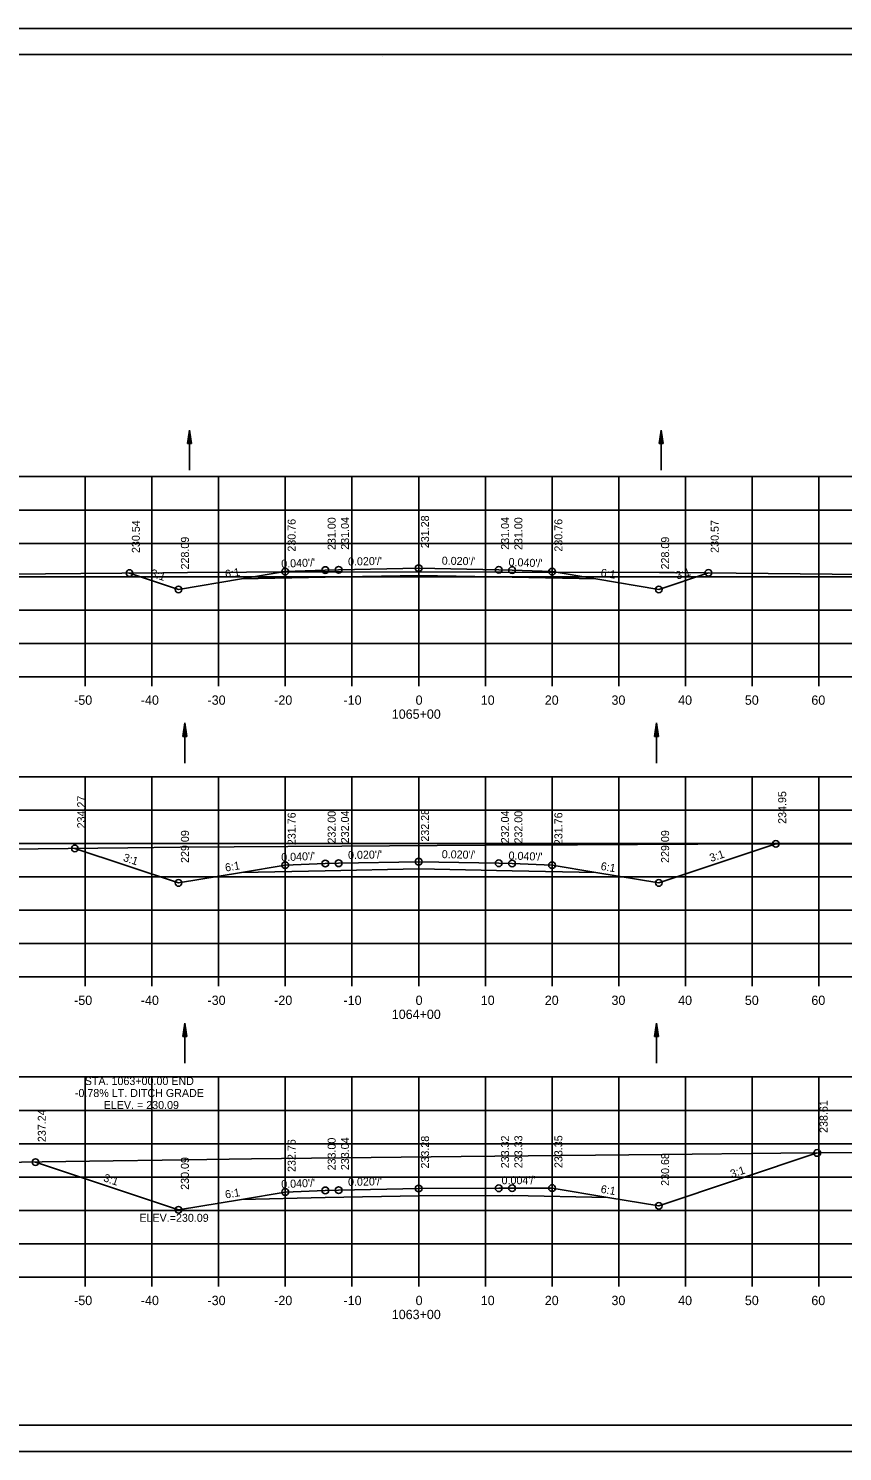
# Model space of a CAD drawing. Extents: x 1386544 to 1388153, y 379785 to 390999.
# Drawn here: x 1387301.2 to 1387423.2, y 388652.2 to 388865.6 of the extents above; entities that cross this region are included whole.
import ezdxf

# ---------------------------------------------------------------- set-up
doc = ezdxf.new("R2010")
doc.units = 0
for name, color, linetype in [('R_Alt Surface', 7, 'Continuous'), ('R_Axis', 7, 'Continuous'), ('R_Axis Annot', 7, 'Continuous'), ('R_Border', 7, 'Continuous'), ('R_Exist Surface', 7, 'Continuous'), ('R_Fin Surface', 7, 'Continuous'), ('R_Grid', 7, 'Continuous'), ('R_No Plot', 7, 'Continuous'), ('R_Water', 7, 'Continuous'), ('R_Xsect Elev', 7, 'Continuous'), ('R_Xsect Slope', 7, 'Continuous')]:
    doc.layers.add(name, color=color, linetype=linetype)

msp = doc.modelspace()

# ---------------------------------------------------------------- linework, layer by layer
at = {"layer": 'R_Alt Surface'}
for points in [[(1387333.11, 388783.04), (1387345.68, 388783.29), (1387359.68, 388783.57), (1387373.68, 388783.29), (1387386.24, 388783.04)], [(1387333.11, 388739.03), (1387345.68, 388739.29), (1387359.68, 388739.57), (1387373.68, 388739.29), (1387386.24, 388739.03)], [(1387333.11, 388690.03), (1387345.68, 388690.29), (1387359.68, 388690.57), (1387373.68, 388690.62), (1387388.03, 388690.33)]]:
    msp.add_lwpolyline(points, dxfattribs=at)
at = {"layer": 'R_Axis'}
for p, q in [((1387209.68, 388768.37), (1387509.68, 388768.37)), ((1387309.68, 388766.97), (1387309.68, 388768.37)), ((1387319.68, 388766.97), (1387319.68, 388768.37)), ((1387329.68, 388766.97), (1387329.68, 388768.37)), ((1387339.68, 388766.97), (1387339.68, 388768.37)), ((1387349.68, 388766.97), (1387349.68, 388768.37)), ((1387359.68, 388766.97), (1387359.68, 388768.37)), ((1387369.68, 388766.97), (1387369.68, 388768.37)), ((1387379.68, 388766.97), (1387379.68, 388768.37)), ((1387389.68, 388766.97), (1387389.68, 388768.37)), ((1387399.68, 388766.97), (1387399.68, 388768.37)), ((1387409.68, 388766.97), (1387409.68, 388768.37)), ((1387419.68, 388766.97), (1387419.68, 388768.37)), ((1387209.68, 388723.37), (1387509.68, 388723.37)), ((1387309.68, 388721.97), (1387309.68, 388723.37)), ((1387319.68, 388721.97), (1387319.68, 388723.37)), ((1387329.68, 388721.97), (1387329.68, 388723.37)), ((1387339.68, 388721.97), (1387339.68, 388723.37)), ((1387349.68, 388721.97), (1387349.68, 388723.37)), ((1387359.68, 388721.97), (1387359.68, 388723.37)), ((1387369.68, 388721.97), (1387369.68, 388723.37)), ((1387379.68, 388721.97), (1387379.68, 388723.37)), ((1387389.68, 388721.97), (1387389.68, 388723.37)), ((1387399.68, 388721.97), (1387399.68, 388723.37)), ((1387409.68, 388721.97), (1387409.68, 388723.37)), ((1387419.68, 388721.97), (1387419.68, 388723.37)), ((1387209.68, 388678.37), (1387509.68, 388678.37)), ((1387309.68, 388676.97), (1387309.68, 388678.37)), ((1387319.68, 388676.97), (1387319.68, 388678.37)), ((1387329.68, 388676.97), (1387329.68, 388678.37)), ((1387339.68, 388676.97), (1387339.68, 388678.37)), ((1387349.68, 388676.97), (1387349.68, 388678.37)), ((1387359.68, 388676.97), (1387359.68, 388678.37)), ((1387369.68, 388676.97), (1387369.68, 388678.37)), ((1387379.68, 388676.97), (1387379.68, 388678.37)), ((1387389.68, 388676.97), (1387389.68, 388678.37)), ((1387399.68, 388676.97), (1387399.68, 388678.37)), ((1387409.68, 388676.97), (1387409.68, 388678.37)), ((1387419.68, 388676.97), (1387419.68, 388678.37))]:
    msp.add_line(p, q, dxfattribs=at)
at = {"layer": 'R_Border'}
for p, q in [((1387201.68, 388861.66), (1387517.86, 388861.66)), ((1387354.2, 388861.4), (1387354.2, 388861.4)), ((1387354.2, 388861.4), (1387354.2, 388861.4)), ((1387517.86, 388656.2), (1387201.68, 388656.2))]:
    msp.add_line(p, q, dxfattribs=at)
at = {"layer": 'R_Exist Surface'}
for points in [[(1387298.42, 388783.73), (1387309, 388783.85), (1387321.3, 388783.96), (1387325.02, 388784), (1387333.85, 388784.07), (1387340.19, 388784.11), (1387348.12, 388784.09), (1387395.81, 388784.01), (1387398.05, 388784), (1387402.48, 388783.95), (1387445.73, 388783.51), (1387463.47, 388783.03), (1387491.83, 388782.07), (1387509.68, 388781.89)], [(1387209.68, 388741.21), (1387233.79, 388741.64), (1387266.18, 388742.12), (1387280.18, 388742.34), (1387316.06, 388742.73), (1387323.9, 388742.8), (1387348.15, 388742.99), (1387376.74, 388743.16), (1387379.36, 388743.18), (1387383.49, 388743.19), (1387410.53, 388743.31), (1387428.61, 388743.34), (1387442.67, 388743.32), (1387468.93, 388743.23), (1387476.16, 388743.21), (1387480.41, 388743.19), (1387509.61, 388742.99), (1387509.68, 388742.99)], [(1387209.68, 388693.86), (1387219.92, 388694.17), (1387223.94, 388694.29), (1387226.86, 388694.37), (1387231.05, 388694.44), (1387275.22, 388695.2), (1387303.21, 388695.63), (1387313.88, 388695.79), (1387321.22, 388695.9), (1387334.59, 388696.08), (1387366.07, 388696.47), (1387396.22, 388696.76), (1387413.99, 388696.93), (1387430.97, 388697.08), (1387461.23, 388697.3), (1387492.16, 388697.2), (1387509.68, 388697.14)]]:
    msp.add_lwpolyline(points, dxfattribs=at)
at = {"layer": 'R_Fin Surface'}
for points in [[(1387316.32, 388783.92), (1387323.68, 388781.46), (1387333.11, 388783.04), (1387339.68, 388784.13), (1387345.68, 388784.37), (1387347.68, 388784.41), (1387359.68, 388784.65), (1387371.68, 388784.41), (1387373.68, 388784.37), (1387379.68, 388784.13), (1387386.24, 388783.04), (1387395.68, 388781.46), (1387403.12, 388783.95)], [(1387308.13, 388742.64), (1387323.68, 388737.46), (1387333.11, 388739.03), (1387339.68, 388740.13), (1387345.68, 388740.37), (1387347.68, 388740.41), (1387359.68, 388740.65), (1387371.68, 388740.41), (1387373.68, 388740.37), (1387379.68, 388740.13), (1387386.24, 388739.03), (1387395.68, 388737.46), (1387413.24, 388743.32)], [(1387302.22, 388695.61), (1387323.67, 388688.46), (1387323.68, 388688.46), (1387333.11, 388690.03), (1387339.68, 388691.13), (1387345.68, 388691.37), (1387347.68, 388691.41), (1387359.68, 388691.65), (1387371.68, 388691.69), (1387373.68, 388691.7), (1387379.68, 388691.72), (1387388.03, 388690.33), (1387395.68, 388689.05), (1387419.45, 388696.98)]]:
    msp.add_lwpolyline(points, dxfattribs=at)
at = {"layer": 'R_Grid'}
for p, q in [((1387209.68, 388798.37), (1387509.68, 388798.37)), ((1387309.68, 388768.37), (1387309.68, 388798.37)), ((1387319.68, 388768.37), (1387319.68, 388798.37)), ((1387329.68, 388768.37), (1387329.68, 388798.37)), ((1387339.68, 388768.37), (1387339.68, 388798.37)), ((1387349.68, 388768.37), (1387349.68, 388798.37)), ((1387359.68, 388768.37), (1387359.68, 388798.37)), ((1387369.68, 388768.37), (1387369.68, 388798.37)), ((1387379.68, 388768.37), (1387379.68, 388798.37)), ((1387389.68, 388768.37), (1387389.68, 388798.37)), ((1387399.68, 388768.37), (1387399.68, 388798.37)), ((1387409.68, 388768.37), (1387409.68, 388798.37)), ((1387419.68, 388768.37), (1387419.68, 388798.37)), ((1387209.68, 388793.37), (1387509.68, 388793.37)), ((1387209.68, 388788.37), (1387509.68, 388788.37)), ((1387209.68, 388783.37), (1387509.68, 388783.37)), ((1387209.68, 388778.37), (1387509.68, 388778.37)), ((1387209.68, 388773.37), (1387509.68, 388773.37)), ((1387209.68, 388768.37), (1387509.68, 388768.37)), ((1387209.68, 388753.37), (1387509.68, 388753.37)), ((1387309.68, 388723.37), (1387309.68, 388753.37)), ((1387319.68, 388723.37), (1387319.68, 388753.37)), ((1387329.68, 388723.37), (1387329.68, 388753.37)), ((1387339.68, 388723.37), (1387339.68, 388753.37)), ((1387349.68, 388723.37), (1387349.68, 388753.37)), ((1387359.68, 388723.37), (1387359.68, 388753.37)), ((1387369.68, 388723.37), (1387369.68, 388753.37)), ((1387379.68, 388723.37), (1387379.68, 388753.37)), ((1387389.68, 388723.37), (1387389.68, 388753.37)), ((1387399.68, 388723.37), (1387399.68, 388753.37)), ((1387409.68, 388723.37), (1387409.68, 388753.37)), ((1387419.68, 388723.37), (1387419.68, 388753.37)), ((1387209.68, 388748.37), (1387509.68, 388748.37)), ((1387209.68, 388743.37), (1387509.68, 388743.37)), ((1387209.68, 388738.37), (1387509.68, 388738.37)), ((1387209.68, 388733.37), (1387509.68, 388733.37)), ((1387209.68, 388728.37), (1387509.68, 388728.37)), ((1387209.68, 388723.37), (1387509.68, 388723.37)), ((1387209.68, 388708.37), (1387509.68, 388708.37)), ((1387309.68, 388678.37), (1387309.68, 388708.37)), ((1387319.68, 388678.37), (1387319.68, 388708.37)), ((1387329.68, 388678.37), (1387329.68, 388708.37)), ((1387339.68, 388678.37), (1387339.68, 388708.37)), ((1387349.68, 388678.37), (1387349.68, 388708.37)), ((1387359.68, 388678.37), (1387359.68, 388708.37)), ((1387369.68, 388678.37), (1387369.68, 388708.37)), ((1387379.68, 388678.37), (1387379.68, 388708.37)), ((1387389.68, 388678.37), (1387389.68, 388708.37)), ((1387399.68, 388678.37), (1387399.68, 388708.37)), ((1387409.68, 388678.37), (1387409.68, 388708.37)), ((1387419.68, 388678.37), (1387419.68, 388708.37)), ((1387209.68, 388703.37), (1387509.68, 388703.37)), ((1387209.68, 388698.37), (1387509.68, 388698.37)), ((1387209.68, 388693.37), (1387509.68, 388693.37)), ((1387209.68, 388688.37), (1387509.68, 388688.37)), ((1387209.68, 388683.37), (1387509.68, 388683.37)), ((1387209.68, 388678.37), (1387509.68, 388678.37))]:
    msp.add_line(p, q, dxfattribs=at)
at = {"layer": 'R_No Plot'}
for p, q in [((1387189.28, 388865.56), (1387522.61, 388865.56)), ((1387189.28, 388652.23), (1387522.61, 388652.23))]:
    msp.add_line(p, q, dxfattribs=at)
for points in [[(1387189.27, 388865.56), (1387522.61, 388865.56), (1387522.61, 388652.22), (1387189.27, 388652.22)], [(1387435.6, 388861.66), (1387455.22, 388861.66), (1387455.22, 388851.78), (1387471.33, 388851.78), (1387494.53, 388851.78), (1387494.53, 388827.45), (1387517.86, 388827.45), (1387517.86, 388656.2), (1387201.68, 388656.2), (1387201.68, 388861.66)]]:
    msp.add_lwpolyline(points, close=True, dxfattribs=at)
for centre in [(1387316.32, 388783.92), (1387339.68, 388784.13), (1387345.68, 388784.37), (1387347.68, 388784.41), (1387359.68, 388784.65), (1387371.68, 388784.41), (1387373.68, 388784.37), (1387379.68, 388784.13), (1387403.12, 388783.95), (1387323.68, 388781.46), (1387395.68, 388781.46), (1387413.24, 388743.32), (1387308.13, 388742.64), (1387339.68, 388740.13), (1387345.68, 388740.37), (1387347.68, 388740.41), (1387359.68, 388740.65), (1387371.68, 388740.41), (1387373.68, 388740.37), (1387379.68, 388740.13), (1387323.68, 388737.46), (1387395.68, 388737.46), (1387419.45, 388696.98), (1387302.22, 388695.61), (1387339.68, 388691.13), (1387345.68, 388691.37), (1387347.68, 388691.41), (1387359.68, 388691.65), (1387371.68, 388691.69), (1387373.68, 388691.7), (1387379.68, 388691.72), (1387323.67, 388688.46), (1387323.68, 388688.46), (1387395.68, 388689.05)]:
    msp.add_circle(centre, 0.5, dxfattribs=at)
at = {"layer": 'R_Water'}
for p, q in [((1387325, 388803.33), (1387325.3, 388805.33)), ((1387325, 388803.33), (1387325.3, 388805.33)), ((1387325.05, 388803.33), (1387325.3, 388804.99)), ((1387325.05, 388803.33), (1387325.3, 388804.99)), ((1387325.1, 388803.33), (1387325.3, 388804.65)), ((1387325.1, 388803.33), (1387325.3, 388804.65)), ((1387325.15, 388803.33), (1387325.3, 388804.32)), ((1387325.15, 388803.33), (1387325.3, 388804.32)), ((1387325.2, 388803.33), (1387325.3, 388803.98)), ((1387325.2, 388803.33), (1387325.3, 388803.98)), ((1387325.25, 388803.33), (1387325.3, 388803.64)), ((1387325.25, 388803.33), (1387325.3, 388803.64)), ((1387325.3, 388799.33), (1387325.3, 388805.33)), ((1387325.6, 388803.33), (1387325.3, 388805.33)), ((1387325.6, 388803.33), (1387325.3, 388805.33)), ((1387325.55, 388803.33), (1387325.3, 388804.99)), ((1387325.55, 388803.33), (1387325.3, 388804.99)), ((1387325.5, 388803.33), (1387325.3, 388804.65)), ((1387325.5, 388803.33), (1387325.3, 388804.65)), ((1387325.45, 388803.33), (1387325.3, 388804.32)), ((1387325.45, 388803.33), (1387325.3, 388804.32)), ((1387325.4, 388803.33), (1387325.3, 388803.98)), ((1387325.4, 388803.33), (1387325.3, 388803.98)), ((1387325.35, 388803.33), (1387325.3, 388803.64)), ((1387325.35, 388803.33), (1387325.3, 388803.64)), ((1387395.73, 388803.33), (1387396.03, 388805.33)), ((1387395.73, 388803.33), (1387396.03, 388805.33)), ((1387395.78, 388803.33), (1387396.03, 388804.99)), ((1387395.78, 388803.33), (1387396.03, 388804.99)), ((1387395.83, 388803.33), (1387396.03, 388804.65)), ((1387395.83, 388803.33), (1387396.03, 388804.65)), ((1387395.88, 388803.33), (1387396.03, 388804.32)), ((1387395.88, 388803.33), (1387396.03, 388804.32)), ((1387395.93, 388803.33), (1387396.03, 388803.98)), ((1387395.93, 388803.33), (1387396.03, 388803.98)), ((1387395.98, 388803.33), (1387396.03, 388803.64)), ((1387395.98, 388803.33), (1387396.03, 388803.64)), ((1387396.03, 388799.33), (1387396.03, 388805.33)), ((1387396.33, 388803.33), (1387396.03, 388805.33)), ((1387396.33, 388803.33), (1387396.03, 388805.33)), ((1387396.28, 388803.33), (1387396.03, 388804.99)), ((1387396.28, 388803.33), (1387396.03, 388804.99)), ((1387396.23, 388803.33), (1387396.03, 388804.65)), ((1387396.23, 388803.33), (1387396.03, 388804.65)), ((1387396.18, 388803.33), (1387396.03, 388804.32)), ((1387396.18, 388803.33), (1387396.03, 388804.32)), ((1387396.13, 388803.33), (1387396.03, 388803.98)), ((1387396.13, 388803.33), (1387396.03, 388803.98)), ((1387396.08, 388803.33), (1387396.03, 388803.64)), ((1387396.08, 388803.33), (1387396.03, 388803.64)), ((1387325, 388803.33), (1387325.6, 388803.33)), ((1387325, 388803.33), (1387325.6, 388803.33)), ((1387395.73, 388803.33), (1387396.33, 388803.33)), ((1387395.73, 388803.33), (1387396.33, 388803.33)), ((1387324.31, 388759.44), (1387324.61, 388761.44)), ((1387324.31, 388759.44), (1387324.61, 388761.44)), ((1387324.36, 388759.44), (1387324.61, 388761.1)), ((1387324.36, 388759.44), (1387324.61, 388761.1)), ((1387324.61, 388755.44), (1387324.61, 388761.44)), ((1387324.91, 388759.44), (1387324.61, 388761.44)), ((1387324.91, 388759.44), (1387324.61, 388761.44)), ((1387324.86, 388759.44), (1387324.61, 388761.1)), ((1387324.86, 388759.44), (1387324.61, 388761.1)), ((1387395.04, 388759.44), (1387395.34, 388761.44)), ((1387395.04, 388759.44), (1387395.34, 388761.44)), ((1387395.09, 388759.44), (1387395.34, 388761.1)), ((1387395.09, 388759.44), (1387395.34, 388761.1)), ((1387395.34, 388755.44), (1387395.34, 388761.44)), ((1387395.64, 388759.44), (1387395.34, 388761.44)), ((1387395.64, 388759.44), (1387395.34, 388761.44)), ((1387395.59, 388759.44), (1387395.34, 388761.1)), ((1387395.59, 388759.44), (1387395.34, 388761.1)), ((1387324.31, 388759.44), (1387324.91, 388759.44)), ((1387324.31, 388759.44), (1387324.91, 388759.44)), ((1387324.42, 388759.44), (1387324.61, 388760.76)), ((1387324.42, 388759.44), (1387324.61, 388760.76)), ((1387324.47, 388759.44), (1387324.61, 388760.42)), ((1387324.47, 388759.44), (1387324.61, 388760.42)), ((1387324.52, 388759.44), (1387324.61, 388760.09)), ((1387324.52, 388759.44), (1387324.61, 388760.09)), ((1387324.57, 388759.44), (1387324.61, 388759.75)), ((1387324.57, 388759.44), (1387324.61, 388759.75)), ((1387324.81, 388759.44), (1387324.61, 388760.76)), ((1387324.81, 388759.44), (1387324.61, 388760.76)), ((1387324.76, 388759.44), (1387324.61, 388760.42)), ((1387324.76, 388759.44), (1387324.61, 388760.42)), ((1387324.71, 388759.44), (1387324.61, 388760.09)), ((1387324.71, 388759.44), (1387324.61, 388760.09)), ((1387324.66, 388759.44), (1387324.61, 388759.75)), ((1387324.66, 388759.44), (1387324.61, 388759.75)), ((1387395.04, 388759.44), (1387395.64, 388759.44)), ((1387395.04, 388759.44), (1387395.64, 388759.44)), ((1387395.15, 388759.44), (1387395.34, 388760.76)), ((1387395.15, 388759.44), (1387395.34, 388760.76)), ((1387395.2, 388759.44), (1387395.34, 388760.42)), ((1387395.2, 388759.44), (1387395.34, 388760.42)), ((1387395.25, 388759.44), (1387395.34, 388760.09)), ((1387395.25, 388759.44), (1387395.34, 388760.09)), ((1387395.3, 388759.44), (1387395.34, 388759.75)), ((1387395.3, 388759.44), (1387395.34, 388759.75)), ((1387395.54, 388759.44), (1387395.34, 388760.76)), ((1387395.54, 388759.44), (1387395.34, 388760.76)), ((1387395.49, 388759.44), (1387395.34, 388760.42)), ((1387395.49, 388759.44), (1387395.34, 388760.42)), ((1387395.44, 388759.44), (1387395.34, 388760.09)), ((1387395.44, 388759.44), (1387395.34, 388760.09)), ((1387395.39, 388759.44), (1387395.34, 388759.75)), ((1387395.39, 388759.44), (1387395.34, 388759.75)), ((1387324.31, 388714.44), (1387324.61, 388716.44)), ((1387324.31, 388714.44), (1387324.61, 388716.44)), ((1387324.36, 388714.44), (1387324.61, 388716.1)), ((1387324.36, 388714.44), (1387324.61, 388716.1)), ((1387324.61, 388710.44), (1387324.61, 388716.44)), ((1387324.91, 388714.44), (1387324.61, 388716.44)), ((1387324.91, 388714.44), (1387324.61, 388716.44)), ((1387324.86, 388714.44), (1387324.61, 388716.1)), ((1387324.86, 388714.44), (1387324.61, 388716.1)), ((1387395.04, 388714.44), (1387395.34, 388716.44)), ((1387395.04, 388714.44), (1387395.34, 388716.44)), ((1387395.09, 388714.44), (1387395.34, 388716.1)), ((1387395.09, 388714.44), (1387395.34, 388716.1)), ((1387395.34, 388710.44), (1387395.34, 388716.44)), ((1387395.64, 388714.44), (1387395.34, 388716.44)), ((1387395.64, 388714.44), (1387395.34, 388716.44)), ((1387395.59, 388714.44), (1387395.34, 388716.1)), ((1387395.59, 388714.44), (1387395.34, 388716.1)), ((1387324.31, 388714.44), (1387324.91, 388714.44)), ((1387324.31, 388714.44), (1387324.91, 388714.44)), ((1387324.42, 388714.44), (1387324.61, 388715.76)), ((1387324.42, 388714.44), (1387324.61, 388715.76)), ((1387324.47, 388714.44), (1387324.61, 388715.42)), ((1387324.47, 388714.44), (1387324.61, 388715.42)), ((1387324.52, 388714.44), (1387324.61, 388715.09)), ((1387324.52, 388714.44), (1387324.61, 388715.09)), ((1387324.57, 388714.44), (1387324.61, 388714.75)), ((1387324.57, 388714.44), (1387324.61, 388714.75)), ((1387324.81, 388714.44), (1387324.61, 388715.76)), ((1387324.81, 388714.44), (1387324.61, 388715.76)), ((1387324.76, 388714.44), (1387324.61, 388715.42)), ((1387324.76, 388714.44), (1387324.61, 388715.42)), ((1387324.71, 388714.44), (1387324.61, 388715.09)), ((1387324.71, 388714.44), (1387324.61, 388715.09)), ((1387324.66, 388714.44), (1387324.61, 388714.75)), ((1387324.66, 388714.44), (1387324.61, 388714.75)), ((1387395.04, 388714.44), (1387395.64, 388714.44)), ((1387395.04, 388714.44), (1387395.64, 388714.44)), ((1387395.15, 388714.44), (1387395.34, 388715.76)), ((1387395.15, 388714.44), (1387395.34, 388715.76)), ((1387395.2, 388714.44), (1387395.34, 388715.42)), ((1387395.2, 388714.44), (1387395.34, 388715.42)), ((1387395.25, 388714.44), (1387395.34, 388715.09)), ((1387395.25, 388714.44), (1387395.34, 388715.09)), ((1387395.3, 388714.44), (1387395.34, 388714.75)), ((1387395.3, 388714.44), (1387395.34, 388714.75)), ((1387395.54, 388714.44), (1387395.34, 388715.76)), ((1387395.54, 388714.44), (1387395.34, 388715.76)), ((1387395.49, 388714.44), (1387395.34, 388715.42)), ((1387395.49, 388714.44), (1387395.34, 388715.42)), ((1387395.44, 388714.44), (1387395.34, 388715.09)), ((1387395.44, 388714.44), (1387395.34, 388715.09)), ((1387395.39, 388714.44), (1387395.34, 388714.75)), ((1387395.39, 388714.44), (1387395.34, 388714.75))]:
    msp.add_line(p, q, dxfattribs=at)

# ---------------------------------------------------------------- texts
at = {"layer": 'R_Axis Annot'}
for s, p in [('-50', (1387308.02, 388764.17)), ('-40', (1387318.02, 388764.17)), ('-30', (1387328.02, 388764.17)), ('-20', (1387338.02, 388764.17)), ('-10', (1387348.41, 388764.17)), ('0', (1387359.22, 388764.17)), ('10', (1387368.99, 388764.17)), ('20', (1387378.59, 388764.17)), ('30', (1387388.59, 388764.17)), ('40', (1387398.59, 388764.17)), ('50', (1387408.59, 388764.17)), ('60', (1387418.56, 388764.17)), ('1065+00', (1387355.65, 388762.07)), ('-50', (1387308.02, 388719.17)), ('-40', (1387318.02, 388719.17)), ('-30', (1387328.02, 388719.17)), ('-20', (1387338.02, 388719.17)), ('-10', (1387348.41, 388719.17)), ('0', (1387359.22, 388719.17)), ('10', (1387368.99, 388719.17)), ('20', (1387378.59, 388719.17)), ('30', (1387388.59, 388719.17)), ('40', (1387398.59, 388719.17)), ('50', (1387408.59, 388719.17)), ('60', (1387418.56, 388719.17)), ('1064+00', (1387355.65, 388717.07)), ('-50', (1387308.02, 388674.17)), ('-40', (1387318.02, 388674.17)), ('-30', (1387328.02, 388674.17)), ('-20', (1387338.02, 388674.17)), ('-10', (1387348.41, 388674.17)), ('0', (1387359.22, 388674.17)), ('10', (1387368.99, 388674.17)), ('20', (1387378.59, 388674.17)), ('30', (1387388.59, 388674.17)), ('40', (1387398.59, 388674.17)), ('50', (1387408.59, 388674.17)), ('60', (1387418.56, 388674.17)), ('1063+00', (1387355.65, 388672.07))]:
    msp.add_text(s, height=1.4, dxfattribs=at).set_placement(p)
at = {"layer": 'R_Xsect Elev'}
for s, p in [('230.54', (1387317.87, 388786.92)), ('230.76', (1387341.23, 388787.13)), ('231.00', (1387347.23, 388787.37)), ('231.04', (1387349.23, 388787.41)), ('231.28', (1387361.23, 388787.65)), ('231.04', (1387373.23, 388787.41)), ('231.00', (1387375.23, 388787.37)), ('230.76', (1387381.23, 388787.13)), ('230.57', (1387404.67, 388786.95)), ('228.09', (1387325.23, 388784.46)), ('228.09', (1387397.23, 388784.46)), ('234.27', (1387309.68, 388745.64)), ('234.95', (1387414.79, 388746.32)), ('232.00', (1387347.23, 388743.37)), ('232.04', (1387349.23, 388743.41)), ('232.28', (1387361.23, 388743.65)), ('232.04', (1387373.23, 388743.41)), ('232.00', (1387375.23, 388743.37)), ('231.76', (1387341.23, 388743.13)), ('231.76', (1387381.23, 388743.13)), ('229.09', (1387325.23, 388740.46)), ('229.09', (1387397.23, 388740.46)), ('237.24', (1387303.77, 388698.61)), ('238.61', (1387421, 388699.98)), ('233.00', (1387347.23, 388694.37)), ('233.04', (1387349.23, 388694.41)), ('233.28', (1387361.23, 388694.65)), ('233.32', (1387373.23, 388694.69)), ('233.33', (1387375.23, 388694.7)), ('233.35', (1387381.23, 388694.72)), ('232.76', (1387341.23, 388694.13)), ('230.68', (1387397.23, 388692.05)), ('230.09', (1387325.22, 388691.46)), ('230.09', (1387325.23, 388691.46))]:
    msp.add_text(s, height=1.2, rotation=90, dxfattribs=at).set_placement(p)
for s, p in [('STA. 1063+00.00 END ', (1387309.61, 388707.17)), ('-0.78% LT. DITCH GRADE', (1387308.13, 388705.37)), ('ELEV. = 230.09', (1387312.45, 388703.57)), ('ELEV.=230.09', (1387317.8, 388686.66))]:
    msp.add_text(s, height=1.2, dxfattribs=at).set_placement(p)
at = {"layer": 'R_Xsect Slope'}
for s, rotation, p in [('3:1', 341.5651, (1387319.37, 388783.43)), ('6:1', 9.4623, (1387330.75, 388783.15)), ("0.040'/'", 2.2906, (1387339.09, 388784.71)), ("0.020'/'", 1.1458, (1387349.1, 388785.04)), ("0.020'/'", 358.8542, (1387363.13, 388785.18)), ("0.040'/'", 357.7094, (1387373.14, 388784.99)), ('6:1', 350.5377, (1387386.91, 388783.43)), ('3:1', 18.4349, (1387398.45, 388782.92)), ('3:1', 341.5651, (1387315.27, 388740.79)), ("0.040'/'", 2.2906, (1387339.09, 388740.71)), ("0.020'/'", 1.1458, (1387349.1, 388741.04)), ("0.020'/'", 358.8542, (1387363.13, 388741.18)), ("0.040'/'", 357.7094, (1387373.14, 388740.99)), ('3:1', 18.4349, (1387403.51, 388740.6)), ('6:1', 9.4623, (1387330.75, 388739.15)), ('6:1', 350.5377, (1387386.91, 388739.43)), ('3:1', 18.4349, (1387406.62, 388693.23)), ('3:1', 341.5651, (1387312.32, 388692.77)), ("0.040'/'", 2.2906, (1387339.09, 388691.71)), ("0.020'/'", 1.1458, (1387349.1, 388692.04)), ("0.004'/'", 0.2061, (1387372.11, 388692.29)), ('6:1', 9.4623, (1387330.75, 388690.15)), ('6:1', 350.5377, (1387386.91, 388691.02))]:
    msp.add_text(s, height=1.2, rotation=rotation, dxfattribs=at).set_placement(p)

doc.saveas('drawing.dxf')
